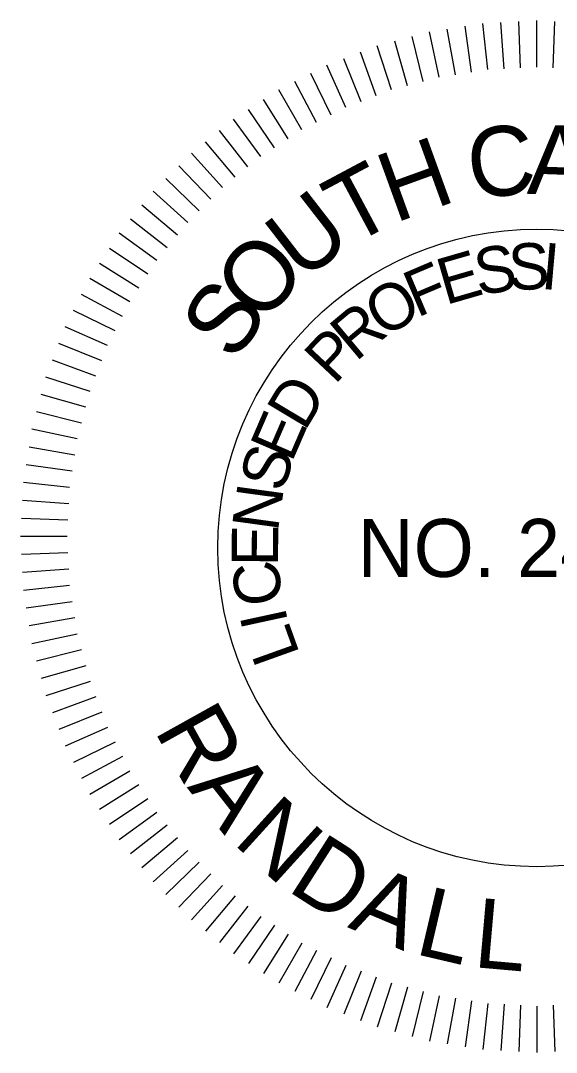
# Model space of a CAD drawing. Extents: x 1964849 to 1967422, y 1116563 to 1122210.
# Drawn here: x 1967303.9 to 1967345, y 1121584.8 to 1121664.1 of the extents above; entities that cross this region are included whole.
import ezdxf

# ---------------------------------------------------------------- set-up
doc = ezdxf.new("R2010")
doc.units = 0
doc.layers.add('RD_TX_PEShield', color=7, linetype='Continuous')

msp = doc.modelspace()

# ---------------------------------------------------------------- linework, layer by layer
at = {"layer": 'RD_TX_PEShield'}
for p, q in [((1967338.519, 1121660.105), (1967338.024, 1121663.626)), ((1967338.519, 1121660.105), (1967338.024, 1121663.626)), ((1967339.762, 1121660.302), (1967339.389, 1121663.843)), ((1967339.762, 1121660.302), (1967339.389, 1121663.843)), ((1967341.018, 1121660.368), (1967340.77, 1121663.915)), ((1967341.018, 1121660.368), (1967340.77, 1121663.915)), ((1967342.273, 1121660.434), (1967342.149, 1121663.987)), ((1967342.273, 1121660.434), (1967342.149, 1121663.987)), ((1967343.529, 1121660.499), (1967343.529, 1121664.059)), ((1967343.529, 1121660.499), (1967343.529, 1121664.059)), ((1967344.786, 1121660.434), (1967344.91, 1121663.987)), ((1967344.786, 1121660.434), (1967344.91, 1121663.987)), ((1967334.82, 1121659.386), (1967333.96, 1121662.836)), ((1967334.82, 1121659.386), (1967333.96, 1121662.836)), ((1967336.035, 1121659.712), (1967335.295, 1121663.194)), ((1967336.035, 1121659.712), (1967335.295, 1121663.194)), ((1967337.278, 1121659.909), (1967336.66, 1121663.41)), ((1967337.278, 1121659.909), (1967336.66, 1121663.41)), ((1967332.391, 1121658.735), (1967331.291, 1121662.121)), ((1967332.391, 1121658.735), (1967331.291, 1121662.121)), ((1967333.606, 1121659.061), (1967332.626, 1121662.479)), ((1967333.606, 1121659.061), (1967332.626, 1121662.479)), ((1967330.043, 1121657.834), (1967328.711, 1121661.131)), ((1967330.043, 1121657.834), (1967328.711, 1121661.131)), ((1967331.216, 1121658.284), (1967330, 1121661.626)), ((1967331.216, 1121658.284), (1967330, 1121661.626)), ((1967328.869, 1121657.383), (1967327.421, 1121660.635)), ((1967328.869, 1121657.383), (1967327.421, 1121660.635)), ((1967327.747, 1121656.812), (1967326.189, 1121660.008)), ((1967327.747, 1121656.812), (1967326.189, 1121660.008)), ((1967325.507, 1121655.67), (1967323.727, 1121658.753)), ((1967325.507, 1121655.67), (1967323.727, 1121658.753)), ((1967326.628, 1121656.242), (1967324.959, 1121659.381)), ((1967326.628, 1121656.242), (1967324.959, 1121659.381)), ((1967324.452, 1121654.985), (1967322.567, 1121658.001)), ((1967324.452, 1121654.985), (1967322.567, 1121658.001)), ((1967323.398, 1121654.301), (1967321.409, 1121657.249)), ((1967323.398, 1121654.301), (1967321.409, 1121657.249)), ((1967322.343, 1121653.616), (1967320.25, 1121656.496)), ((1967322.343, 1121653.616), (1967320.25, 1121656.496)), ((1967321.365, 1121652.824), (1967319.176, 1121655.626)), ((1967321.365, 1121652.824), (1967319.176, 1121655.626)), ((1967320.388, 1121652.033), (1967318.103, 1121654.757)), ((1967320.388, 1121652.033), (1967318.103, 1121654.757)), ((1967319.411, 1121651.241), (1967317.028, 1121653.887)), ((1967319.411, 1121651.241), (1967317.028, 1121653.887)), ((1967318.521, 1121650.352), (1967316.051, 1121652.909)), ((1967318.521, 1121650.352), (1967316.051, 1121652.909)), ((1967317.632, 1121649.463), (1967315.075, 1121651.933)), ((1967317.632, 1121649.463), (1967315.075, 1121651.933)), ((1967316.743, 1121648.573), (1967314.097, 1121650.955)), ((1967316.743, 1121648.573), (1967314.097, 1121650.955)), ((1967315.951, 1121647.596), (1967313.227, 1121649.881)), ((1967315.951, 1121647.596), (1967313.227, 1121649.881)), ((1967315.16, 1121646.619), (1967312.358, 1121648.808)), ((1967315.16, 1121646.619), (1967312.358, 1121648.808)), ((1967314.368, 1121645.641), (1967311.488, 1121647.734)), ((1967314.368, 1121645.641), (1967311.488, 1121647.734)), ((1967313.683, 1121644.586), (1967310.735, 1121646.574)), ((1967313.683, 1121644.586), (1967310.735, 1121646.574)), ((1967312.999, 1121643.532), (1967309.983, 1121645.416)), ((1967312.999, 1121643.532), (1967309.983, 1121645.416)), ((1967312.313, 1121642.477), (1967309.23, 1121644.257)), ((1967312.313, 1121642.477), (1967309.23, 1121644.257)), ((1967311.742, 1121641.356), (1967308.603, 1121643.025)), ((1967311.742, 1121641.356), (1967308.603, 1121643.025)), ((1967311.172, 1121640.236), (1967307.976, 1121641.795)), ((1967311.172, 1121640.236), (1967307.976, 1121641.795)), ((1967310.601, 1121639.115), (1967307.348, 1121640.563)), ((1967310.601, 1121639.115), (1967307.348, 1121640.563)), ((1967310.15, 1121637.941), (1967306.853, 1121639.273)), ((1967310.15, 1121637.941), (1967306.853, 1121639.273)), ((1967309.699, 1121636.768), (1967306.358, 1121637.984)), ((1967309.699, 1121636.768), (1967306.358, 1121637.984)), ((1967309.248, 1121635.593), (1967305.863, 1121636.693)), ((1967309.248, 1121635.593), (1967305.863, 1121636.693)), ((1967308.923, 1121634.378), (1967305.505, 1121635.358)), ((1967308.923, 1121634.378), (1967305.505, 1121635.358)), ((1967308.598, 1121633.164), (1967305.148, 1121634.024)), ((1967308.598, 1121633.164), (1967305.148, 1121634.024)), ((1967308.272, 1121631.949), (1967304.79, 1121632.689)), ((1967308.272, 1121631.949), (1967304.79, 1121632.689)), ((1967308.075, 1121630.706), (1967304.574, 1121631.323)), ((1967308.075, 1121630.706), (1967304.574, 1121631.323)), ((1967307.879, 1121629.465), (1967304.358, 1121629.96)), ((1967307.879, 1121629.465), (1967304.358, 1121629.96)), ((1967307.682, 1121628.222), (1967304.141, 1121628.594)), ((1967307.682, 1121628.222), (1967304.141, 1121628.594)), ((1967307.616, 1121626.966), (1967304.069, 1121627.214)), ((1967307.616, 1121626.966), (1967304.069, 1121627.214)), ((1967307.55, 1121625.711), (1967303.997, 1121625.835)), ((1967307.55, 1121625.711), (1967303.997, 1121625.835)), ((1967307.484, 1121624.454), (1967303.924, 1121624.454)), ((1967307.484, 1121624.454), (1967303.924, 1121624.454)), ((1967307.55, 1121623.198), (1967303.997, 1121623.074)), ((1967307.55, 1121623.198), (1967303.997, 1121623.074)), ((1967307.616, 1121621.943), (1967304.069, 1121621.695)), ((1967307.616, 1121621.943), (1967304.069, 1121621.695)), ((1967307.682, 1121620.687), (1967304.141, 1121620.315)), ((1967307.682, 1121620.687), (1967304.141, 1121620.315)), ((1967307.879, 1121619.444), (1967304.358, 1121618.949)), ((1967307.879, 1121619.444), (1967304.358, 1121618.949)), ((1967308.075, 1121618.203), (1967304.574, 1121617.586)), ((1967308.075, 1121618.203), (1967304.574, 1121617.586)), ((1967308.272, 1121616.96), (1967304.79, 1121616.22)), ((1967308.272, 1121616.96), (1967304.79, 1121616.22)), ((1967308.598, 1121615.745), (1967305.148, 1121614.885)), ((1967308.598, 1121615.745), (1967305.148, 1121614.885)), ((1967308.923, 1121614.531), (1967305.505, 1121613.551)), ((1967308.923, 1121614.531), (1967305.505, 1121613.551)), ((1967309.248, 1121613.316), (1967305.863, 1121612.216)), ((1967309.699, 1121612.141), (1967306.358, 1121610.925)), ((1967309.699, 1121612.141), (1967306.358, 1121610.925)), ((1967310.15, 1121610.968), (1967306.853, 1121609.636)), ((1967310.15, 1121610.968), (1967306.853, 1121609.636)), ((1967310.601, 1121609.794), (1967307.348, 1121608.346)), ((1967310.601, 1121609.794), (1967307.348, 1121608.346)), ((1967311.172, 1121608.673), (1967307.976, 1121607.114)), ((1967311.172, 1121608.673), (1967307.976, 1121607.114)), ((1967311.742, 1121607.553), (1967308.603, 1121605.884)), ((1967311.742, 1121607.553), (1967308.603, 1121605.884)), ((1967312.313, 1121606.432), (1967309.23, 1121604.652)), ((1967312.313, 1121606.432), (1967309.23, 1121604.652)), ((1967312.999, 1121605.377), (1967309.983, 1121603.493)), ((1967312.999, 1121605.377), (1967309.983, 1121603.493)), ((1967313.683, 1121604.323), (1967310.735, 1121602.335)), ((1967313.683, 1121604.323), (1967310.735, 1121602.335)), ((1967314.368, 1121603.268), (1967311.488, 1121601.175)), ((1967314.368, 1121603.268), (1967311.488, 1121601.175)), ((1967315.16, 1121602.29), (1967312.358, 1121600.101)), ((1967315.16, 1121602.29), (1967312.358, 1121600.101)), ((1967315.951, 1121601.313), (1967313.227, 1121599.028)), ((1967315.951, 1121601.313), (1967313.227, 1121599.028)), ((1967316.743, 1121600.336), (1967314.097, 1121597.954)), ((1967316.743, 1121600.336), (1967314.097, 1121597.954)), ((1967317.632, 1121599.446), (1967315.075, 1121596.976)), ((1967317.632, 1121599.446), (1967315.075, 1121596.976)), ((1967318.521, 1121598.557), (1967316.051, 1121596)), ((1967318.521, 1121598.557), (1967316.051, 1121596)), ((1967319.411, 1121597.668), (1967317.028, 1121595.022)), ((1967319.411, 1121597.668), (1967317.028, 1121595.022)), ((1967320.388, 1121596.876), (1967318.103, 1121594.152)), ((1967320.388, 1121596.876), (1967318.103, 1121594.152)), ((1967321.365, 1121596.085), (1967319.176, 1121593.283)), ((1967321.365, 1121596.085), (1967319.176, 1121593.283)), ((1967322.343, 1121595.293), (1967320.25, 1121592.413)), ((1967322.343, 1121595.293), (1967320.25, 1121592.413)), ((1967323.398, 1121594.608), (1967321.409, 1121591.66)), ((1967323.398, 1121594.608), (1967321.409, 1121591.66)), ((1967324.452, 1121593.924), (1967322.567, 1121590.908)), ((1967324.452, 1121593.924), (1967322.567, 1121590.908)), ((1967325.507, 1121593.239), (1967323.727, 1121590.156)), ((1967325.507, 1121593.239), (1967323.727, 1121590.156)), ((1967326.628, 1121592.667), (1967324.959, 1121589.528)), ((1967326.628, 1121592.667), (1967324.959, 1121589.528)), ((1967327.747, 1121592.097), (1967326.189, 1121588.901)), ((1967327.747, 1121592.097), (1967326.189, 1121588.901)), ((1967328.869, 1121591.526), (1967327.421, 1121588.274)), ((1967328.869, 1121591.526), (1967327.421, 1121588.274)), ((1967330.043, 1121591.075), (1967328.711, 1121587.778)), ((1967330.043, 1121591.075), (1967328.711, 1121587.778)), ((1967331.216, 1121590.625), (1967330, 1121587.283)), ((1967331.216, 1121590.625), (1967330, 1121587.283)), ((1967332.391, 1121590.174), (1967331.291, 1121586.788)), ((1967332.391, 1121590.174), (1967331.291, 1121586.788)), ((1967333.606, 1121589.848), (1967332.626, 1121586.43)), ((1967333.606, 1121589.848), (1967332.626, 1121586.43)), ((1967334.82, 1121589.523), (1967333.96, 1121586.073)), ((1967334.82, 1121589.523), (1967333.96, 1121586.073)), ((1967336.035, 1121589.197), (1967335.295, 1121585.715)), ((1967336.035, 1121589.197), (1967335.295, 1121585.715)), ((1967337.278, 1121589), (1967336.66, 1121585.499)), ((1967337.278, 1121589), (1967336.66, 1121585.499)), ((1967338.519, 1121588.804), (1967338.024, 1121585.283)), ((1967338.519, 1121588.804), (1967338.024, 1121585.283)), ((1967339.762, 1121588.607), (1967339.389, 1121585.066)), ((1967339.762, 1121588.607), (1967339.389, 1121585.066)), ((1967341.018, 1121588.541), (1967340.77, 1121584.994)), ((1967341.018, 1121588.541), (1967340.77, 1121584.994)), ((1967342.273, 1121588.475), (1967342.149, 1121584.922)), ((1967342.273, 1121588.475), (1967342.149, 1121584.922)), ((1967343.529, 1121588.409), (1967343.529, 1121584.849)), ((1967343.529, 1121588.409), (1967343.529, 1121584.849)), ((1967344.786, 1121588.475), (1967344.91, 1121584.922)), ((1967344.786, 1121588.475), (1967344.91, 1121584.922))]:
    msp.add_line(p, q, dxfattribs=at)
msp.add_circle((1967343.529, 1121623.576), 24.475, dxfattribs=at)

# ---------------------------------------------------------------- texts
for s, height, rotation, p in [('C', 5.34, 6.88322, (1967338.523, 1121650.314)), ('A', 5.34, 357.94482, (1967342.739, 1121650.767)), ('H', 5.34, 19.91024, (1967332.625, 1121648.498)), ('T', 5.34, 28.09472, (1967329.189, 1121646.692)), ('U', 5.34, 37.77255, (1967325.507, 1121643.952)), ('O', 5.34, 47.45038, (1967322.338, 1121640.632)), ('S', 3.56, 1.78995, (1967341.379, 1121643.366)), ('I', 3.56, 354.88899, (1967343.773, 1121643.481)), ('E', 3.56, 16.18428, (1967336.527, 1121642.21)), ('S', 3.56, 8.69092, (1967339.017, 1121642.964)), ('F', 3.56, 23.08525, (1967334.339, 1121641.234)), ('S', 5.34, 54.90268, (1967320.305, 1121637.74)), ('O', 3.56, 31.78688, (1967331.774, 1121639.64)), ('R', 3.56, 39.89024, (1967329.627, 1121637.823)), ('P', 3.56, 46.7912, (1967328.016, 1121636.049)), ('D', 3.56, 59.07401, (1967325.717, 1121632.463)), ('E', 3.56, 66.56738, (1967324.71, 1121630.065)), ('S', 3.56, 73.46834, (1967324.067, 1121627.756)), ('N', 3.56, 82.16997, (1967323.659, 1121624.764)), ('E', 3.56, 89.66334, (1967323.674, 1121622.162)), ('C', 3.56, 97.7667, (1967324.071, 1121619.378)), ('I', 3.56, 102.25114, (1967324.459, 1121617.869)), ('L', 3.56, 109.74451, (1967325.366, 1121615.431)), ('R', 5.34, 299.14926, (1967314.127, 1121609.603)), ('A', 5.34, 308.08766, (1967316.655, 1121605.204)), ('N', 5.34, 317.7655, (1967320.126, 1121600.948)), ('D', 5.34, 327.44333, (1967324.263, 1121597.336)), ('A', 5.34, 337.12116, (1967328.949, 1121594.47)), ('L', 5.34, 346.799, (1967334.049, 1121592.433)), ('L', 5.34, 354.98347, (1967338.579, 1121591.401))]:
    msp.add_text(s, height=height, rotation=rotation, dxfattribs=at).set_placement(p)
msp.add_text('NO. 24265', height=4.4501, dxfattribs=at).set_placement((1967329.776, 1121621.351))

doc.saveas('drawing.dxf')
